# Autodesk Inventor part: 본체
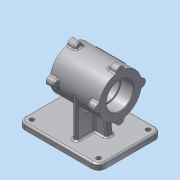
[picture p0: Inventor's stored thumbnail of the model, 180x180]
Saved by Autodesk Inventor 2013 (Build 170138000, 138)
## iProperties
Created: 2015-12
Part Number: 본체
Material: 알루미늄 6061
Document SubType Name: Modeling
Designer: dgall
Density: 2.71 g/cm^3
Mass: 1165.29 g
Surface Area: 815.622 cm^2
Volume: 429.997 cm^3
Author: dgall
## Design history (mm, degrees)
sketch "스케치1"
  geometry: L1 (-70, 55)-(70, 55); L2 (70, 55)-(70, -55); L3 (70, -55)-(-70, -55); L4 (-70, -55)-(-70, 55); 3 further points
  constraints: 8 end point, 2 midpoint, 2 parallel, 1 horizontal, 1 horizontal alignment, 1 perpendicular, 1 vertical alignment
  dimensions: "d0" = 140 distance of L1.start L1.end; "d2" = 110 distance of L1.end L2.end
extrude "돌출1" new body sketch "스케치1" distance "d3" = 10; taper "d4" = 0 deg
node "작업 평면1"
sketch "스케치2"
  geometry: L1 (0, 110)-(0, 0) reference; L2 (0, 0)-(-10, 0) reference; L3 (-10, 110)-(-10, 0) reference; L4 (0, 110)-(-10, 110) reference; C1 r 37 at (70, 55); 2 further points
  constraints: 1 centre point, 1 horizontal alignment, 1 midpoint
  dimensions: "d6" = 74 diameter of C1; "d8" = 80 distance from line of L3 C1.centre
extrude "돌출2" join sketch "스케치2" stored distance "d9" = 85; taper "d10" = 0 deg
node "작업 평면2"
sketch "스케치3"
  geometry: L1 (37.5, 107)-(37.5, 33) reference; L2 (122.5, 33)-(122.5, 107) reference; L3 (37.5, 70)-(122.5, 70); L4 (37.5, 93.5)-(59.5, 93.5); L5 (59.5, 93.5)-(59.5, 91); L6 (59.5, 91)-(100.5, 91); L7 (100.5, 91)-(100.5, 93.5); L8 (100.5, 93.5)-(122.5, 93.5); L9 (37.5, 33)-(122.5, 33) reference; 2 further points
  constraints: 12 end point, 3 midpoint, 3 parallel, 2 perpendicular, 2 point on line
  dimensions: "d11" = 47 diameter of L4 L3; "d13" = 42 diameter of L6 L3; "d14" = 47 diameter of L8 L3; "d15" = 22 distance of L7.end L8.end; "d16" = 22 distance of L4.start L4.end
revolve "회전1" sketch "스케치3" stored, may be unused: angle "d17" = 90 deg
sketch "스케치4"
  geometry: L1 (37.5, 107)-(37.5, 33) reference; L2 (122.5, 33)-(122.5, 107) reference; L3 (37.5, 33)-(122.5, 33) reference; L4 (80, 33)-(80, 0); L5 (59.706, 38.325)-(55, 0); L6 (100.294, 38.325)-(105, 0); L7 (0, 0)-(140, 0) reference; L8 (59.706, 38.325)-(100.294, 38.325); 1 further point
  constraints: 8 end point, 3 point on line, 1 midpoint, 1 parallel, 1 perpendicular
  dimensions: "d21" = 97 deg angle of L7 L5; "d22" = 97 deg angle of L7 L6; "d23" = 25 distance of L5.end L4.end; "d24" = 50 distance of L6.end L5.end
extrude "돌출3" join sketch "스케치4" stored distance "d25" = 12; taper "d26" = 0 deg
node "작업 평면3"
sketch "스케치5"
  geometry: L1 (61, 0)-(61, 33.49) reference; L2 (49, 0)-(61, 0) reference; L3 (49, 33.49)-(49, 0) reference; L4 (0, 0)-(110, 0) reference; L5 (110, 0)-(110, -10) reference; L6 (0, -10)-(110, -10) reference; L7 (0, 0)-(0, -10) reference; L8 (55, 70)-(55, 0); L9 (18, 70)-(18, 0); L10 (92, 70)-(92, 0); C1 r 23.5 at (55, 70) reference; C2 r 37 at (55, 70) reference; A1 r 37 centre (55, 70) between (49, 33.49) and (61, 33.49) reference; A2 r 37 centre (55, 70) between (18, 70) and (92, 70); 1 further point
  constraints: 6 end point, 2 point on circle, 2 point on line, 1 centre point, 1 coincident, 1 concentric, 1 midpoint, 1 parallel
  dimensions: "d28" = 37 distance between parallel lines of L8 L9; "d30" = 74 distance between parallel lines of L10 L9
extrude "돌출4" join sketch "스케치5" stored distance "d31" = 8; taper "d32" = 0 deg
sketch "스케치6"
  geometry: C1 r 23.5 at (0, 0) reference; C2 r 37 at (0, 0) reference; 1 further point
node "작업 평면4"
sketch "스케치7"
  geometry: L1 (37.5, 107)-(122.5, 107) reference; L2 (122.5, 33)-(122.5, 107) reference; L3 (122.5, 107)-(122.5, 114); L4 (122.5, 114)-(110.048, 114); L5 (110.048, 114)-(105.405, 101.245); L6 (122.5, 101.245)-(105.405, 101.245); 1 further point
  constraints: 8 end point, 1 collinear, 1 parallel, 1 perpendicular, 1 point on line
  dimensions: "d35" = 7 distance of L1.end L3.end
extrude "돌출5" join sketch "스케치7" stored distance "d36" = 14; taper "d37" = 0 deg
fillet "모깎기1" dims "d38" = 7
sketch "스케치8"
  geometry: C1 r 23.5 at (-55, 70) reference; C2 r 37 at (-55, 70); C3 r 2 at (-55, 107); A1 r 7 centre (-55, 107) between (-48, 107) and (-62, 107) reference; 1 further point
  constraints: 2 centre point, 2 coincident
  dimensions: "d39" = 74 diameter of C2; "d40" = 4 diameter of C3
hole "구멍1" sketch "스케치8" at (-55, 107) diameter "d41" = 3.242; stored, may be unused: countersink angle "d45" = 90 deg, drill point angle "d47" = 118 deg; dims "d42" = 9, "d43" = 4, "d44" = 2, "d46" = 11
sketch "스케치9"
  geometry: L1 (37.5, 107)-(107.5, 107) reference; L2 (107.5, 107)-(110.048, 114) reference; L3 (122.5, 114)-(110.048, 114) reference; L4 (122.5, 114)-(122.5, 107) reference; 1 further point
fillet "모깎기2" dims "d51" = 3
sketch "스케치10"
  geometry: L1 (-32.5, 107)-(35.399, 107) reference; L2 (-32.5, 107)-(-32.5, 114); L3 (-32.5, 114)-(-20.048, 114); L4 (-20.048, 114)-(-16.185, 103.387); L5 (-16.185, 103.387)-(-32.5, 103.387); L6 (-32.5, 107)-(-32.5, 103.387); 1 further point
  constraints: 10 end point, 3 perpendicular, 1 parallel
  dimensions: "d55" = 7 distance between parallel lines of L3 L1; "d57" = 110 deg angle of L1 L4
extrude "돌출6" join sketch "스케치10" stored distance "d58" = 14; taper "d59" = 0 deg
sketch "스케치11" dims "d60" = 74
  geometry: C1 r 23.5 at (55, 70) reference; C2 r 2 at (55, 107); 2 further points
  constraints: 1 centre point, 1 coincident, 1 vertical alignment, 2 other
  dimensions: "d61" = 4 diameter of C2
hole "구멍2" sketch "스케치11" at (55, 107) diameter "d62" = 3.242; stored, may be unused: countersink angle "d66" = 90 deg, drill point angle "d68" = 118 deg; dims "d63" = 9, "d64" = 4, "d65" = 2, "d67" = 11
fillet "모깎기3" dims "d69" = 7
fillet "모깎기4" dims "d73" = 3
sketch "스케치12"
  geometry: L1 (-70, 55)-(70, 55) reference; L2 (-70, -55)-(-70, 55) reference; C1 r 4 at (-58, 43); 1 further point
  constraints: 1 centre point
  dimensions: "d77" = 8 diameter of C1; "d79" = 12 distance from line of L2 C1.centre; "d80" = 12 distance from line of L1 C1.centre
extrude "돌출7" cut sketch "스케치12" stored distance "d81" = 14; taper "d82" = 0 deg
fillet "모깎기5" dims "d89" = 12
fillet "모깎기6" dims "d90" = 3
fillet "모깎기7" dims "d91" = 3
fillet "모깎기8" dims "d92" = 0.3
chamfer "모따기1" distance "d93" = 1; stored, may be unused: second distance "d94" = 2, angle "d95" = 45 deg
node "작업 평면5"
sketch "스케치13"
  geometry: 1 further point
sketch "스케치14"
  geometry: L1 (-70, 55)-(-70, 4.362); L2 (-70, 55)-(-96.163, 28.837); 1 further point
  constraints: 4 end point, 1 vertical
  dimensions: "d97" = 45 deg angle of L1 L2
node "작업 평면6"
sketch "스케치15"
  geometry: L1 (42.5, -18.921)-(42.5, 18.921) reference; L2 (-42.5, 18.921)-(-42.5, -18.921) reference; 3 further points
  constraints: 1 horizontal alignment, 1 midpoint, 1 other
  dimensions: "d98" = 42.5 distance from line of L2 point (0, 0)
feature "엠보싱1" sketch "스케치15" dims "d99" = 0.5, "d100" = 0
node "솔리드1"
pattern_circular "원형 패턴1" dims "d49" = 360 deg
pattern_circular "원형 패턴2" dims angle "d53" = 360 deg
pattern_circular "원형 패턴3" dims "d71" = 360 deg
pattern_circular "원형 패턴4" dims angle "d75" = 360 deg
pattern_linear "직사각형 패턴1" dims "d85" = 116, "d88" = 86
node "투영된 루프1"
node "투영된 루프2"
node "투영된 루프3"
node "투영된 루프4"
node "투영된 루프5"
node "투영된 루프6"
other parameters: "d96" = -42.5
